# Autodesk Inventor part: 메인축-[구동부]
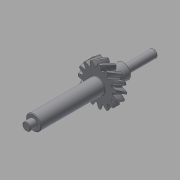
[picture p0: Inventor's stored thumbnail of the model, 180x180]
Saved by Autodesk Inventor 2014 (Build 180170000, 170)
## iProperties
Created: 2016-12
Part Number: 메인축-[구동부]
Material: 강철, 탄소
Document SubType Name: Modeling
Designer: mduedu
Categories: <?xml version="1.0" encoding="UTF-16"?> <MemberInstance><Categories><FamilyTemplate><FamilyTemplateParameter ValueType="xs:double" Id="1" ObjectReferenceKey="da
Density: 7.87 g/cm^3
Appearance: Default
Mass: 199.401 g
Surface Area: 86.9137 cm^2
Volume: 25.3368 cm^3
CustomPartVersion: 1
Author: mduedu
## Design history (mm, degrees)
sketch "Sketch1"
  geometry: C1 r 19.321 at (0, 0)
  constraints: 1 centre point
  dimensions: "d0" = 38.64102 diameter of C1 (= da_da)
extrude "Extrusion1" new body sketch "Sketch1" distance "d1" = 10 (= da_b); taper "d2" = 0 deg
workplane "Work Plane2"
sketch "Sketch2"
  geometry: C1 r 19.321 at (0, 0) reference; C2 r 17.321 at (0, 0)
  constraints: 1 centre point, 1 coincident
  dimensions: "d3" = 34.64102 diameter of C2 (= da_dw)
feature "피치 지름" sketch "Sketch2" dims "d4" = 10, "d5" = 0
workplane "Work Plane8"
workplane "Work Plane9"
feature "스퍼 기어" dims "da_b" = 10, "da_d" = 34.64102, "da_aw" = 43.87862, "da_da" = 38.64102, "da_df" = 29.64102, "da_dw" = 34.64102, angle "da_beta" = 30 deg, "da_lefttooth" = 0, "da_righttooth" = 10
sketch "스케치3"
  geometry: C1 r 7.5 at (0, 0); 1 further point
  constraints: 1 centre point, 1 coincident
  dimensions: "d49" = 15 diameter of C1
extrude "돌출2" join sketch "스케치3" distance "d50" = 64; taper "d51" = 0 deg
sketch "스케치4"
  geometry: C1 r 4 at (0, 0); 1 further point
  constraints: 1 centre point, 1 coincident
  dimensions: "d52" = 8 diameter of C1
extrude "돌출3" join sketch "스케치4" distance "d53" = 7; taper "d54" = 0 deg
sketch "스케치5"
  geometry: C1 r 7.5 at (0, 0) reference; 1 further point
extrude "돌출4" join sketch "스케치5" distance "d55" = 16; taper "d56" = 0 deg
sketch "스케치6"
  geometry: C1 r 4 at (0, 0); 1 further point
  constraints: 1 centre point, 1 coincident
  dimensions: "d57" = 8 diameter of C1
extrude "돌출5" join sketch "스케치6" distance "d58" = 30; taper "d59" = 0 deg
chamfer "모따기1" distance "d60" = 0.5; stored, may be unused: second distance "d61" = 2, angle "d62" = 45 deg
fillet "모깎기1" dims "d63" = 0.5
body "Solid1"
body "Srf1"
other parameters: "d16" = 43.87862 (= da_aw), "d17" = 0, "d34" = 12 deg (computed from da_z), "d39" = 0, "d41" = 0, "d43" = 43.87862 (= da_aw), "d46" = 43.87862 (= da_aw), "d47" = 0, "d48" = 0
